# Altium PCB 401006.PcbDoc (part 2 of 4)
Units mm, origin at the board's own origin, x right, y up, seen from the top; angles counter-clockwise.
Board outline 117 x 63.5 mm, 4 copper layers (Top Layer, Mid-Layer 1, Mid-Layer 2, Bottom Layer), stack 1.68 mm thick; 205 components, 151 nets, 838 pads, 1570 vias.
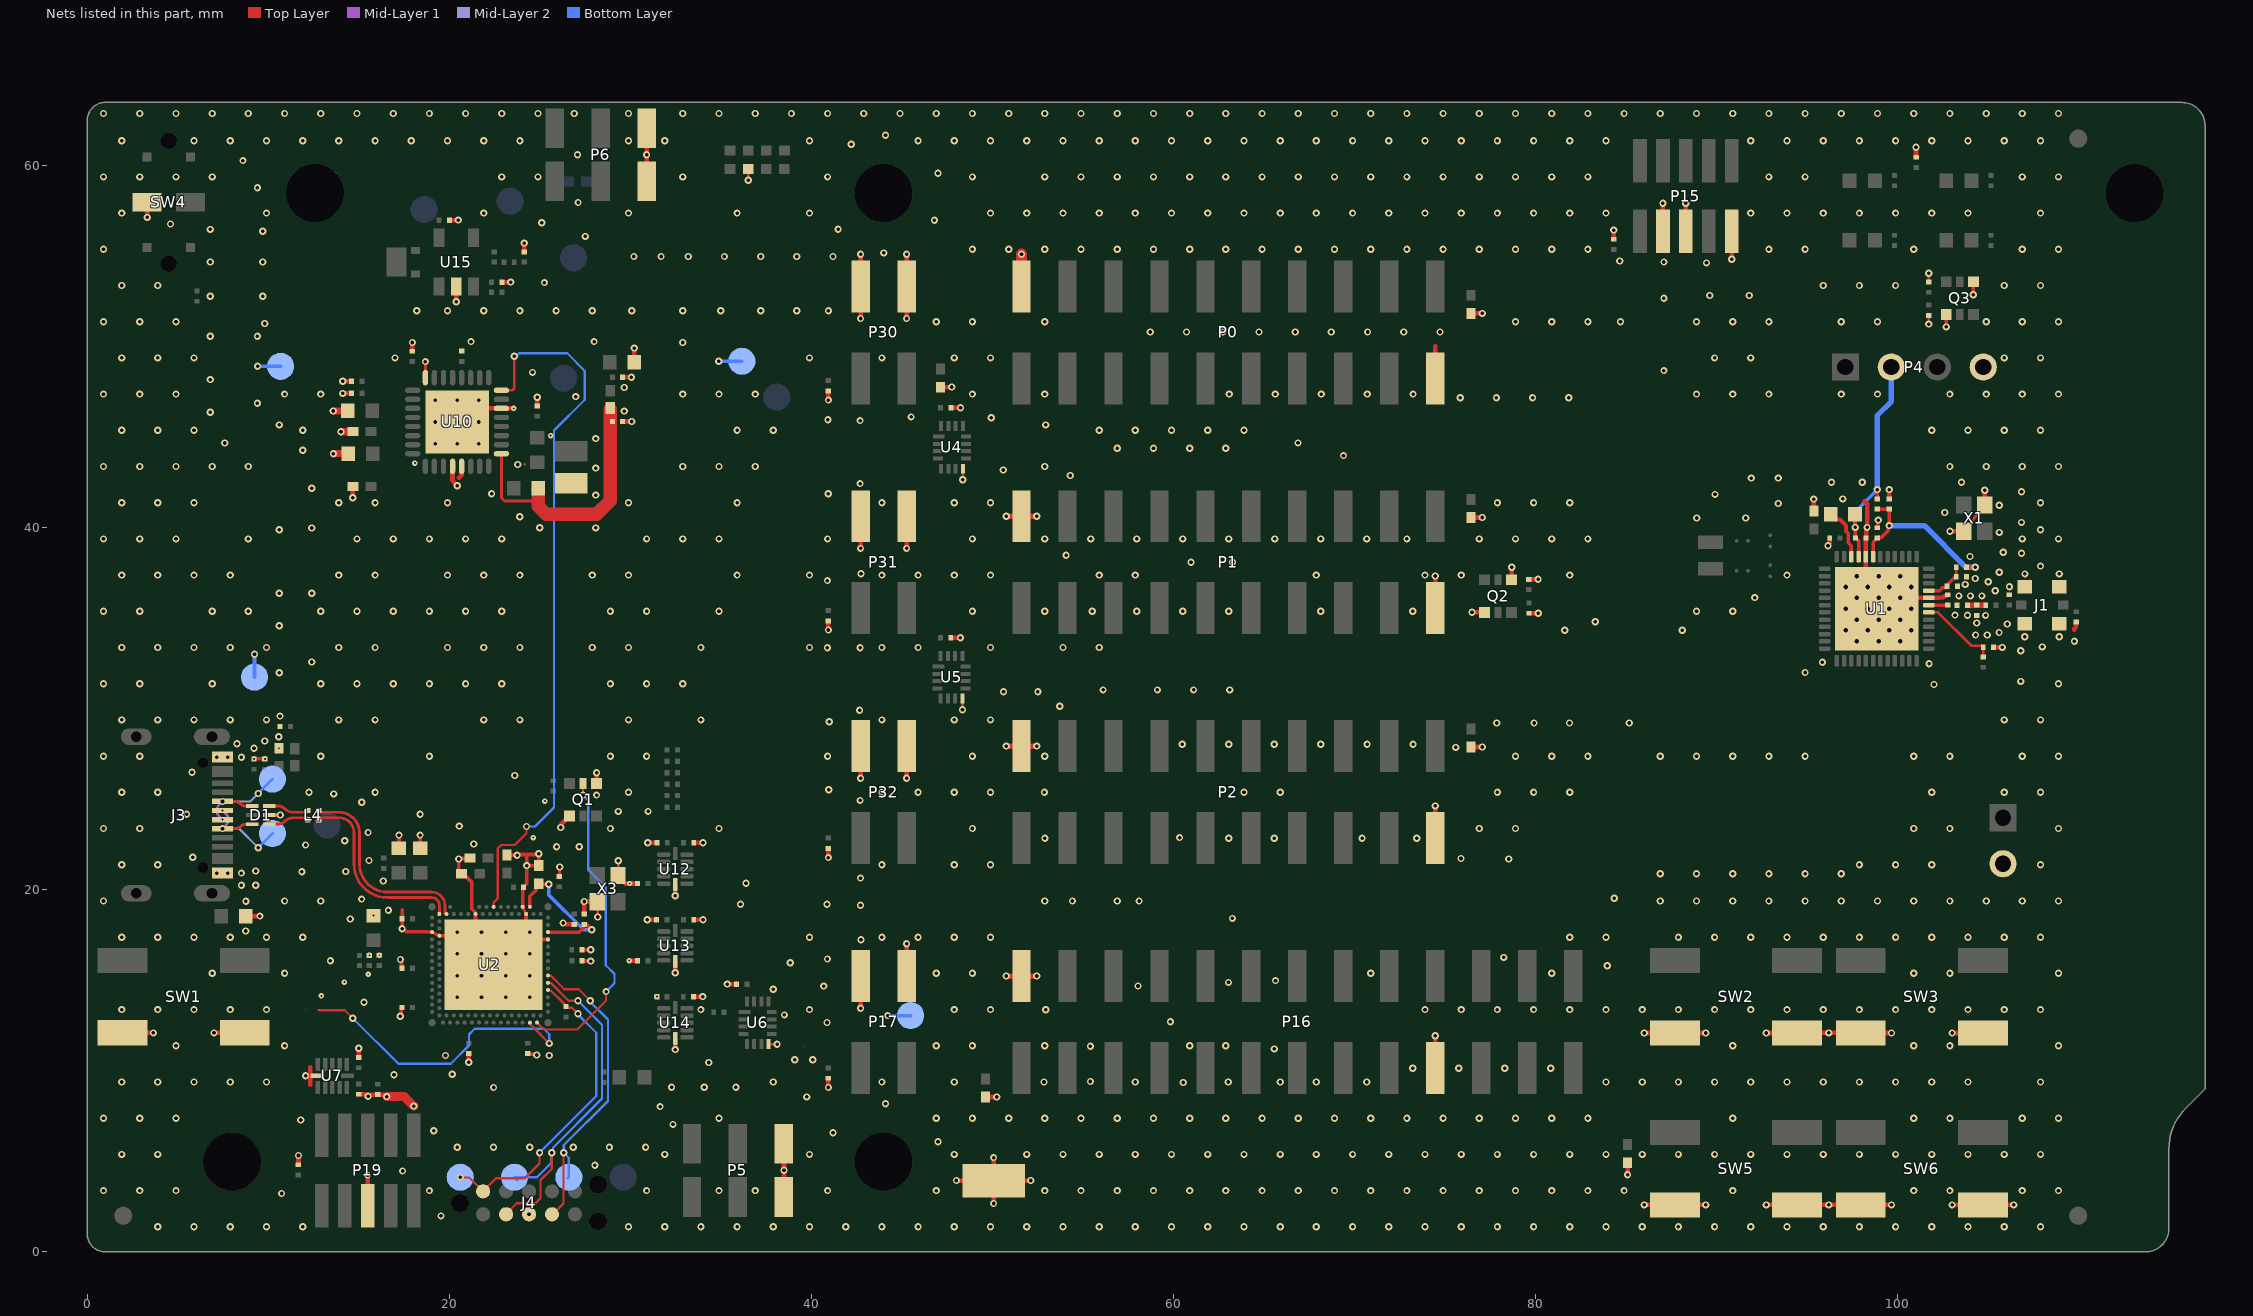
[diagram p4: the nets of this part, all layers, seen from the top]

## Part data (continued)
C41: library part C0402-100n, "Capacitor, X7R, ±10%", Manufacturer=N.A., Part number IPS=00000005296, Part number NEMS=100200184
C42 C43 C54 C58: library part C0603-4µ7-10V-X7S, "Capacitor, X7S, ±10%, 10V", Manufacturer=N.A., Part number IPS=00000001779, Part number NEMS=100200351, Supplier Part Number 1=445-14258-1-ND
C47: library part C0402-1µ0-16V-X5R, "Capacitor, Ceramic, X5R, ±10%, 16V", Manufacturer=Murata, Manufacturer Part Number=GRT155R61C105KE01D, Part number IPS=N.A., Part number NEMS=100200452, Supplier Part Number 1=490-12255-1-ND
C59: library part C0603-10n-100V-X7R, "Capacitor, X7R, ±10%, 100V", Manufacturer=Murata, Manufacturer Part Number=GCM188R72A103KA37D, Part number IPS=N.A., Part number NEMS=100200349, Supplier Part Number 1=490-4781-1-ND
D1: "TVS DIODE 5.5VWM 6XSON", Manufacturer=Nexperia, Part number IPS=N.A., Part number NEMS=101300202, Supplier Part Number 1=1727-4161-1-ND
FB1: library part FB0201-120R@100M-200mA-BLM03AG121SN1D, "Ferrite Bead, 120 Ohm @ 100MHz, 200mA, 500 mOhm Max", Manufacturer=Murata, Manufacturer Part Number=BLM03AG121SN1D, Part number IPS=N.A., Part number NEMS=100300419, Supplier Part Number 1=490-5622-1-ND
FB2 R1: library part R0201-0R-5%-0.05W-RC0201JR-070RL, "0 Ohms Jumper 0.05W, 1/20W Chip Resistor 0201 (0603 Metric) Moisture Resistant Thick Film", Manufacturer=Yageo, Manufacturer Part Number=RC0201JR-070RL, Part number IPS=N.A., Part number NEMS=100100652, Supplier Part Number 1=311-0.0NCT-ND
FB3 FB4: library part FB0402-120R@100M-500mA, "Ferrite Bead, 120 Ohm @ 100MHz, 500mA, 250 mOhm Max", Manufacturer=Murata, Manufacturer Part Number=BLM15AG121SN1D, Part number IPS=00000009954, Part number NEMS=100300099, Part number Norautron=265230631, Supplier Part Number 1=490-1005-1-ND
Fid1 Fid2 Fid3: library part Fid-Mark, "Fiducial Mark", Manufacturer=N.A., Part number NEMS=100500073
H1 H2 H3 H4 H5: library part MountingHole_3.2_M3, "Mounting hole, 3.2mm, M3, no annular", Manufacturer=N.A., Part number NEMS=101200008
J1: "Coaxial Connector with Switch", Manufacturer=Murata, Part number IPS=00000009955, Part number NEMS=100500400, Part number Norautron=26030338, Supplier Part Number 1=490-4981-1-ND
J3: library part SD-80259-1021, "USB-C Receptacle, 16 Pin, USB 2.0", Manufacturer="Bellweather Electronic Corp.", Part number IPS=N.A., Part number NEMS=100500830
J4: library part TC2050-IDC-NLFP, "CBL PLUG-OF-NAILS 10-PIN", Manufacturer="Tag-Connect LLC", Part number IPS=N.A., Part number NEMS=100500463, Supplier Part Number 1=TC2050-IDC-NL-ND
JP1: library part "SHUNT JUMPER 2.54mm Black Vertical", "Shunt Jumper 2.54mm Black, open top", Manufacturer=WCON, Manufacturer Part Number=3710-6001OS0B05, Part number IPS=N.A., Part number NEMS=100500728
L1: library part L0603-4µ7-MLZ1608M4R7WT000, "Inductor, 120mA, ±20%, 0.65R", Manufacturer="TDK Corporation", Manufacturer Part Number=MLZ1608M4R7WT000, Part number IPS=N.A., Part number NEMS=100300440, Supplier Part Number 1=445-6390-2-ND
L2: library part L0201-2n6-HQ-Murata, "Inductor, 600mA, ±0.1ｎH, 120mOhm", Manufacturer=Murata, Part number IPS=N.A., Part number NEMS=100300213, Supplier Part Number 1=490-13907-1-ND
L3: library part L0201-3n3-HQ-Murata, "Inductor, 500mA, ±0.1ｎH, 170mOhm", Manufacturer=Murata, Part number IPS=N.A., Part number NEMS=100300220, Supplier Part Number 1=490-13921-1-ND
L4: "2 Line Common Mode Choke, 90Ohm @ 100MHz, Imax=100mA, DCR=4Ohm, VDC=5V,  -40°C ~ 85°C", Manufacturer="Murata Electronics", Part number IPS=N.A., Part number NEMS=100300513, Supplier Part Number 1=490-DLM0NSM900HY2DCT-ND
L8: library part L0806-2µ2-2500mA-73mOhm-CIGT201610EH2R2MNE, "Inductor, Irms=2.5A, Isat=2.9A, ±20%, DCR=73mΩ", Manufacturer="Samsung Electro-Mechanics America", Manufacturer Part Number=CIGT201610EH2R2MNE, Part number IPS=N.A., Part number NEMS=100300400, Part number Norautron=26521789, Supplier Part Number 1=1276-6901-1-ND
LABEL1: library part Label_12x12, "PCA version label, stick-on, 12x12mm", Manufacturer="Ellco Etikett", Manufacturer Part Number=A33512‐01, Part number IPS=N.A., Part number NEMS=101200028
LABEL2: library part Label_20x40, "Early Access Label", Manufacturer=NA, Part number IPS=N.A., Part number NEMS=101200035
LD1 LD2 LD3 LD4 LD5: library part "VS 25C7M5", "LED, Green, 0603, 573nm, Vf=2.0V, 24mcd, - 40 to +85°C", Manufacturer="Victory Electronics", Part number IPS="00000001274, 00000009961", Part number NEMS=101400097, Part number Norautron=26313411, Supplier Part Number 1=N.A.
LOGO1: library part "Nordic Logo lying", "Nordic logo lying", Manufacturer=N.A., Part number NEMS=101100001
LOGO2: "Segger logo, small size", Manufacturer=N.A., Part number NEMS=101100004
LOGO3: library part "WEEE Symbol 3x4.5mm", "WEEE Directive symbol", Manufacturer=N.A., Part number NEMS=101100006
NT2: library part "2 pin starpoint", "Starpoint", Manufacturer=N.A., Part number NEMS=100500603
P0 P1 P2: library part "Pin Header 2x10 SMD, 2.54mm", "Pin Header 2x10, 2.54mm (100mil) SMD", Manufacturer=WCON, Manufacturer Part Number=1125-1210S0M116CR09, Part number IPS=N.A., Part number NEMS=100500738
P3: "Pin List 1x2, 2.54mm (100mil)", Manufacturer=N.A., Part number NEMS=100500297
P4: "Pin List 1x4, 2.54mm (100mil)", Manufacturer=N.A., Part number NEMS=100500309
P5 P6: library part "Pin List 1x3 SMD", "Pin List 1x3, 2.54mm (100mil), SMD", Manufacturer=WCON, Manufacturer Part Number=1125-1103S0M116CR04, Part number IPS=N.A., Part number NEMS=100500306, Part number Norautron=26470016
P15 P19: library part "Pin Header 2x5 SMD, 1.27mm, KS", "Pin Header 2x5, 1.27mm (50mil), SMD, Keying Shroud", Manufacturer=WCON, Manufacturer Part Number=3132-10MS0BK00R5, Part number IPS=N.A., Part number NEMS=100500261
P16: library part "Pin Header 2x13 SMD, 2.54mm", "Pin Header 2x13, 2.54mm (100mil) SMD", Manufacturer=WCON, Manufacturer Part Number=1125-1213S0M116CR09, Part number IPS=N.A., Part number NEMS=100500908
P17 P30 P31 P32: "Pin Header 2x2, SMD, 2.54mm (100mil)", Manufacturer=WCON, Manufacturer Part Number=1125-1202S0M116CR03, Part number IPS=N.A., Part number NEMS=100500770
Q1 Q2 Q3: "MOSFET 2N-CH 60V 0.17A TSSOP6 (SOT363)", Manufacturer=Nexperia, Manufacturer Part Number=NX138AKSX, Part number IPS=N.A., Part number NEMS=101300207, Supplier Part Number 1=1727-2732-2-ND
Q4: library part PBSS4330PA,115, "30V, 3A, 2.1W, G=270, NPN Transistor", Manufacturer=Nexperia, Part number IPS=N.A., Part number NEMS=101300184, Supplier Part Number 1=1727-5112-1-ND‎
R2 R3 R19 R20: library part R0201-680, "Resistor, ±1%, 0.05W", Manufacturer=N.A., Part number NEMS=100100040
R4 R37 R41 R42: library part R0201-10k, "Resistor, ±1%, 0.05W", Manufacturer=N.A., Part number IPS=00000001255, Part number NEMS=100100065, Part number Norautron=26107101
R5: library part R0201-560, "Resistor, ±1%, 0.05W", Manufacturer=N.A., Part number NEMS=100100038
R6 R8 R13 R14 R15 R16 R21 R22 R31 R32 R56: library part R0201-100k, "Resistor, ±1%, 0.05W", Manufacturer=N.A., Part number IPS=00000001419, Part number NEMS=100100080, Part number Norautron=26108487
R7: library part R0201-47R, "Resistor, ±1%, 0.05W", Manufacturer=N.A., Part number IPS=00000004794, Part number NEMS=100100022, Part number Norautron=26108300
R9 R38: library part R0201-0R, "Resistor, ±5%, 0.05W", Manufacturer=N.A., Part number IPS=00000003245, Part number NEMS=100100001
R10 R11 R12 R18 R27: library part R0201-1M0, "Resistor, ±1%, 0.05W", Manufacturer=N.A., Part number IPS=00000001418, Part number NEMS=100100093, Part number Norautron=26107108
R24: library part R0402-TBD, "Chip Res 0402", Manufacturer=N.A., Part number NEMS=100100282
R25 R28 R29 R30: library part R0402-0R, "Resistor, ±5%, 0.063W", Manufacturer=N.A., Part number IPS=00000007128, Part number NEMS=100100109, Supplier Part Number 1=146-9661
R26: library part R0201-47k, "Resistor, ±1%, 0.05W", Manufacturer=N.A., Part number IPS=00000001423, Part number NEMS=100100076
R36: library part R0201-1k0, "Resistor, ±1%, 0.05W", Manufacturer=N.A., Part number IPS=00000005786, Part number NEMS=100100043
R40: library part R0201-2R2, "Resistor, ±1%, 0.05W", Manufacturer=N.A., Part number NEMS=100100006, Part number Norautron=26470029
R43: library part R0201-33k, "Resistor, ±1%, 0.05W", Manufacturer=N.A., Part number IPS=00000001708, Part number NEMS=100100073
SB1: Manufacturer=N.A., Part number NEMS=100500458
SB2: library part "Solderbridge Shorted", "Shorted Solderbridge", Manufacturer=N.A., Part number NEMS=100500459
SB3 SB4: library part "Solderbridge Shorted 0.4mm", "Shorted Solderbridge", Manufacturer=N.A., Part number NEMS=100500561
SB5 SB6: library part "Solderbridge 0.4mm", Manufacturer=N.A., Part number NEMS=100500560
SW1 SW2 SW3 SW5 SW6: library part Switch-PB-6.2x6.3mm-SMD, "Tactile Switch, SPNO, SMD, 160gf, 6.2x6.3x2.5mm", Manufacturer=Dailywell, Manufacturer Part Number=TS604VM1-025BR-R, Part number IPS=00000007812, Part number NEMS="101500001, 101500133", Part number Norautron=N.A.
SW4: library part Switch-Slide-RA-J-Lead-DPDT-8.5x3.5mm_C&K, "SMD slide Switch (ON-ON)", Manufacturer=C&K, Manufacturer Part Number=JS202011JAQN, Part number IPS=00000007811, Part number NEMS=101500037, Part number Norautron=N.A., Supplier Part Number 1=CKN10722CT-ND
TP1 TP3 TP4 TP5 TP6 TP8 TP9 TP10 TP11 TP12 TP13 TP14 TP15 TP16 TP17 TP18: library part TP_SMD_Ø1.5MM, "1.5mm circular SMD testpad", Manufacturer="Nordic Semiconductor", Manufacturer Part Number=N.A., Part number NEMS=100500477
TP22: library part "TP - S1751-46R", "PC TEST POINT TIN SMD L", Manufacturer=Harwin, Manufacturer Part Number=S1751-46R, Part number IPS=N.A., Part number NEMS=100500525, Supplier Part Number 1=952-1478-1-ND
U1: "Multi-protocol Bluetooth Low Energy, IEEE 802.15.4 and 2.4GHz proprietary Wireless MCU", Manufacturer="Nordic Semiconductor", Part number IPS=N.A., Part number NEMS=102000422
U2: "Multi-protocol Bluetooth Low Energy, IEEE 802.15.4, ANT and 2.4GHz proprietary system-on-chip", Manufacturer="Nordic Semiconductor", Part number IPS=N.A., Part number NEMS=102000153
U4 U5 U6: "Low-Capacitance, 1:1 (SPST) 4-Channel, analog switch", Manufacturer="Texas Instruments", Manufacturer Part Number=TMUX1511RSVR, Part number IPS=N.A., Part number NEMS=101900847, Supplier Part Number 1=296-53443-2-ND
U7 U12 U13 U14: library part TXB0104RUTR, "4-Bit Bidirectional Level-Shifter/Voltage Translator with Automatic Direction Sensing", Manufacturer="Texas Instruments", Part number IPS=N.A., Part number NEMS=101900856, Supplier Part Number 1=296-25888-2-ND
U10: "Li-Ion/Li-Polymer USB-C battery charger with high efficiency buck regulators, LDOs or load switches, LED drivers, TWI and VBUSOUT", Manufacturer="Nordic Semiconductor", Part number IPS=N.A., Part number NEMS=102000291
U15: library part TLV271CW5-7, "Dual rail to rail CMOS Amplifier", Manufacturer="Diodes Incorporated", Part number IPS=N.A., Part number NEMS=101900398, Supplier Part Number 1=TLV271CW5-7DICT-ND
X1: library part XTAL_SMD2016_32MHz_8pF_Kyocera, "XTAL SMD 2016, 32MHz, Cl=8pF, Tot: ±40ppm", Manufacturer=Kyocera, Manufacturer Part Number=CX2016DB32000D0WZRC1, Part number IPS=00000007827, Part number NEMS=101600039, Part number Norautron=26511136, Supplier Part Number 1=1253-1586-1-ND
X2: library part XTAL_SMD2012_32.768kHz_9pF_TXC, "XTAL SMD 2012, 32.768kHz, 9pF, ±20ppm", Manufacturer="TXC Corporation", Manufacturer Part Number=9HT11-32.768KDZC-T, Part number IPS=N.A., Part number NEMS=101600107, Supplier Part Number 1=887-1426-2-ND
X3: library part XTAL_SMD2016_32MHz_8pF_Golledge, "XTAL SMD 2016, 32MHz, Cl=8pF, Tol: ±10ppm, Stab: ±15ppm", Manufacturer=Golledge, Manufacturer Part Number=MP06003, Part number IPS=00000001431, Part number NEMS=101600041, Part number Norautron=N.A.

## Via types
v1: diameter 0.4, hole 0.2, Top Layer to Bottom Layer, tented both sides, 1458 vias
v2: diameter 0.3, hole 0.1, Top Layer to Mid-Layer 1, tented top, 71 vias
v3: diameter 0.5, hole 0.25, Top Layer to Bottom Layer, tented both sides, 24 vias
v4: diameter 0.3, hole 0.1, Top Layer to Mid-Layer 1, tented both sides, 17 vias

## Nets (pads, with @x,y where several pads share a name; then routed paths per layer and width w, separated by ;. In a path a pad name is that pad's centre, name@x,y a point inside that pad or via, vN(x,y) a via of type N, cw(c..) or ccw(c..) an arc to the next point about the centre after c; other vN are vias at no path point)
ANT: C6.2 L2.1 U1.31 | length 0.9
  Top Layer w0.2: U1.31@101.893,35.73 102.75,35.73 C6.2@102.751,35.729
DBGR''_N: D1.3 L4.1 | length 2.3
  Top Layer w0.153: D1.3@10.065,24.634 10.567,24.634 cw(c10.567,24.164) 10.899,24.496 ccw(c11.408,25.005) 11.408,24.285 12.101,24.285 ccw(c12.101,24.384) L4.1@12.2,24.384
DBGR''_P: D1.1 L4.2 | length 2.3
  Top Layer w0.153: D1.1@10.065,23.634 10.567,23.634 ccw(c10.567,24.104) 10.899,23.772 cw(c11.408,23.263) 11.408,23.982 12.101,23.982 cw(c12.101,23.884) L4.2@12.2,23.884
DBGR'_N: D1.4 J3.A7 J3.B7 TP17.1 | length 6.2
  Top Layer w0.153: J3.B7@7.49,24.884 8.127,24.884 cw(c8.127,24.318) 8.527,24.718 ccw(c8.73,24.921) 8.73,24.634 D1.4@9.135,24.634
  Mid-Layer 1 w0.127: v2(7.485,23.884) 7.271,24.098 cw(c7.544,24.372) 7.157,24.372 cw(c7.604,24.372) 7.288,24.687 v1(7.485,24.884)
  Mid-Layer 2 w0.125: v1(7.485,24.884) 9.015,24.884 v1(9.455,25.324)
  Bottom Layer w0.153: v1(9.455,25.324) TP17.1@10.24,26.115
DBGR'_P: D1.6 J3.A6 J3.B6 TP18.1 | length 6.5
  Top Layer w0.153: v1(7.485,23.384) 8.174,23.384 ccw(c8.174,23.873) 8.519,23.528 cw(c8.776,23.271) 8.776,23.634 D1.6@9.135,23.634
  Mid-Layer 1 w0.127: v1(7.485,23.384) 7.682,23.581 ccw(c7.366,23.896) 7.813,23.896 ccw(c7.426,23.896) 7.699,24.17 v4(7.485,24.384)
  Mid-Layer 2 w0.125: v1(7.485,23.384) 8.393,23.384 v1(9.455,22.322)
  Bottom Layer w0.153: v1(9.455,22.322) TP18.1@10.24,23.113
DBGR_BUTTON: SB2.2 U2.AL27 | length 17.4
  Top Layer w0.125: SB2.2@12.8,13.364 12.815,13.35 14.237,13.35 v1(14.675,12.912) ; U2.AL27@24.46,12.664 24.46,12.637 24.51,12.587 24.51,12.555 24.631,12.434 24.631,12.427 v1(25.54,11.518)
  Top Layer w0.15: U2.AL27@24.46,12.622 U2.AL27@24.46,12.637
  Bottom Layer w0.125: v1(14.675,12.912) 17.2,10.387 20.087,10.387 21.1,11.4 21.1,12.009 21.416,12.325 25.244,12.325 25.54,12.03 v1(25.54,11.518)
DBGR_LED: Q1.2 U2.AL29 | length 17.4
  Top Layer w0.125: U2.AL29@24.86,12.664 25.237,12.288 27.083,12.288 28.663,13.868 28.663,14.368 v1(28.675,14.381) ; v1(27.401,25.234) Q1.2@27.401,25.71
  Bottom Layer w0.125: v1(27.401,25.234) 27.693,24.942 27.693,21.097 28.658,20.131 28.658,15.831 29.14,15.348 29.14,14.834 v1@28.675,14.369
DBGR_N: L4.4 U2.B4 | length 11.2
  Top Layer w0.153: L4.4@12.8,24.384 ccw(c12.898,24.384) 12.898,24.285 13.925,24.285 cw(c13.925,23.158) 15.053,23.158 15.053,21.422 ccw(c16.6,21.422) 16.6,19.875 19.033,19.875 cw(c19.033,19.138) 19.77,19.138 19.77,18.755 ccw(c19.86,18.755) U2.B4@19.86,18.664
DBGR_P: L4.3 U2.B2 | length 10.7
  Top Layer w0.153: L4.3@12.8,23.884 cw(c12.898,23.884) 12.898,23.982 13.925,23.982 cw(c13.925,23.158) 14.75,23.158 14.75,21.422 ccw(c16.6,21.422) 16.6,19.572 19.033,19.572 cw(c19.033,19.138) 19.467,19.138 19.467,18.664 U2.B2@19.46,18.664
DBGR_RESET: J4.10 R6.1 TP4.1 U2.AC31 | length 17.6
  Top Layer w0.125: v1(20.616,4.115) 21.107,4.115 J4.10@21.878,3.344 22.609,4.075 24.2,4.075 25.001,4.876 v1(25.001,5.475) ; U2.AC31@25.46,14.464 25.479,14.445 25.616,14.445 26.372,13.689 26.372,13.628 26.517,13.483 26.792,13.483 v1(27.125,13.15)
  Bottom Layer w0.125: v1(25.001,5.475) 28.132,8.605 28.132,12.107 27.125,13.114 v1(27.125,13.15)
DBGR_SWDCLK: J4.4 TP6.1 U2.W31 | length 17.8
  Top Layer w0.125: U2.W31@25.46,15.264 25.471,15.254 25.624,15.254 26.363,14.515 27.16,14.515 v1(27.8,13.875) ; J4.4@25.688,2.074 25.724,2.074 26.324,2.674 26.324,5.459 v1(26.34,5.475)
  Bottom Layer w0.125: TP6.1@26.558,4.067 TP6.1@26.564,4.062 ; TP6.1@26.616,4.125 26.616,5.198 v1(26.34,5.475) 26.34,5.903 28.775,8.339 28.775,12.832 v1@27.8,13.808
DBGR_SWDIO: J4.2 TP5.1 U2.AA31 | length 20.4
  Top Layer w0.125: J4.2@23.148,2.074 23.148,2.099 23.74,2.69 24.771,2.69 25.053,2.972 25.053,3.968 25.667,4.582 v1(25.667,5.475) ; U2.AA31@25.46,14.864 25.471,14.854 25.624,14.854 26.603,13.875 v1(27.125,13.875)
  Bottom Layer w0.125: TP5.1@23.616,4.125 24.851,4.125 25.667,4.94 v1(25.667,5.475) 25.738,5.547 25.738,5.76 28.452,8.473 28.452,12.548 v1(27.125,13.875)
  Bottom Layer w0.15: TP5.1@23.616,4.115 TP5.1@23.759,3.972
DCC: L1.1 U1.46 | length 2.8
  Top Layer w0.2: L1.1@96.316,40.758 96.316,40.733 96.591,40.458 96.834,40.458 97.169,40.123 97.169,39.819 97.296,39.692 97.296,39.187 97.468,39.014 U1.46@97.468,38.555
DECA: C2.2 C12.2 FB1.2 FB2.2 U1.43 | length 9.8
  Top Layer w0.2: U1.43@98.668,38.555 98.668,39.204 C12.2@98.896,39.432 98.931,39.467 99.119,39.467 99.499,39.847 99.499,40.066 v1(99.556,40.123) C2.2@99.556,41.032 FB1.2@98.896,41.032 ; FB2.2@103.83,37.821 v1(104.307,37.821)
  Bottom Layer w0.3: v1(99.556,40.123) 101.504,40.124 103.807,37.821 v1(104.307,37.821)
DECD: C1.2 FB1.1 L1.2 P4.2 U1.45 | length 12.5
  Top Layer w0.2: L1.2@97.677,40.798 v1(97.677,40.022) 97.677,39.461 C1.2@97.698,39.439 97.698,39.424 97.733,39.389 97.748,39.389 97.868,39.269 97.868,38.78 U1.45@97.868,38.555 ; FB1.1@98.896,41.602 v1(98.896,42.11)
  Bottom Layer w0.2: v1(97.677,40.022) 97.677,40.891 v1(98.896,42.11)
  Bottom Layer w0.3: v1(98.896,42.11) 98.896,46.202 99.674,46.98 P4.2@99.674,48.884
DERF: C5.2 C13.2 FB2.1 U1.33 | length 2.2
  Top Layer w0.15: C13.2@103.26,37.297 FB2.1@103.26,37.821
  Top Layer w0.2: U1.33@101.893,36.53 102.356,36.53 102.525,36.699 C5.2@102.716,36.699 ; C5.2@102.753,36.779 102.788,36.814 102.788,36.883 103.153,37.247 103.225,37.247 103.26,37.282 C13.2@103.26,37.297
GND: C1.1 C2.1 C3.1 C5.1 C6.1 C9.1 C10.2 C11.1 C12.1 C13.1 C14.2 C15.2 C16.1 C18.2 C20.2 C22.2 C23.1 C25.1 C26.1 C28.1 C29.2 C30.2 C31.2 C32.1 C33.2 C34.2 C35.2 C36.2 C37.2 C38.1 C39.1 C40.2 C41.1 C42.2 C43.2 C44.2 C45.1 C46.1 C47.1 C48.1 C49.2 C50.1 C51.1 C52.1 C53.1 C54.2 C55.1 C56.1 C57.1 C58.2 C59.2 C62.1 C63.1 C64.1 C67.2 C68.1 C69.2 C70.1 C72.2 C73.1 C74.2 C75.2 C76.2 C77.2 C78.2 C79.2 C80.2 C81.2 C82.1 C83.1 C84.1 D1.2 J1.2 J3.A1 J3.A12 J4.3 NT2.1 P0.2 P0.19 P1.2 P1.19 P2.2 P2.19 P3.2 P4.4 P5.1 P6.1 P15.3 P15.5 P15.9 P16.2 P16.19 P17.2 P17.4 P19.5 P30.2 P30.4 P31.2 P31.4 P32.2 P32.4 Q1.1 Q1.4 Q2.1 Q2.4 Q3.1 Q3.4 R4.1 R7.2 R10.2 R11.2 R12.2 R18.1 R26.2 R27.2 R30.2 R32.2 R37.1 R42.1 R56.2 SW1.1 SW2.1 SW3.1 SW4.2 SW5.1 SW6.1 TP12.1 TP13.1 TP14.1 TP15.1 TP22.1 U1.32 U1.44 U1.49 U2.104 U2.A25 U2.B12 U2.B26 U2.G1 U2.H2 U2.J31 U4.8 U5.8 U6.8 U7.6 U10.6 U10.16 U10.28 U10.29 U10.33 U12.6 U13.6 U14.6 U15.2 X1.2 X1.4 X3.2 X3.4 | length 169.9
  Top Layer w0.15: U10.16@18.678,48.31 U10.16@18.692,48.296 v1(18.692,49.183) ; C37.2@26.096,20.744 26.103,20.751 26.103,21.258 v1(26.11,21.265) ; v1(28.21,18.497) X3.4@28.21,19.315 ; X3.2@29.35,20.821 v1(29.35,21.608) ; v1(36.525,59.207) R30.2@36.525,59.83 ; U6.8@37.65,11.475 v1(38.121,11.475) ; v1(48.36,29.952) U5.8@48.36,30.561 ; v1(48.378,42.653) U4.8@48.378,43.262 ; v1(101.743,51.254) R27.2@101.743,51.729 ; R11.2@101.743,53.585 v1(101.743,54.06) ; X1.4@104.03,40.209 X1.2@104.48,40.859
  Top Layer w0.165: U2.A25@24.06,19.064 U2.B26@24.26,18.664
  Top Layer w0.187: U2.G1@19.06,17.664 U2.H2@19.46,17.464 U2.104@20.16,17.464 ; 21.245,20.052 21.245,18.96 21.453,18.752 21.453,18.672 U2.B12@21.46,18.664
  Top Layer w0.188: 18.183,17.694 18.832,17.694 18.856,17.669 19.055,17.669 U2.G1@19.06,17.664
  Top Layer w0.2: v4(9.225,27.235) v4(9.825,27.235) ; D1.2@10.065,24.134 v1(10.673,24.134) ; C42.2@17.231,22.302 v1(17.231,23.024) ; v1(17.308,13.017) 17.365,13.074 17.365,13.436 C20.2@17.428,13.499 ; v1(17.313,16.149) 17.369,16.094 17.369,15.659 C18.2@17.404,15.624 ; 17.404,18.9 17.404,18.864 C80.2@17.404,18.401 v1(17.404,17.852) 17.485,17.852 17.644,17.694 18.183,17.694 ; C43.2@18.4,22.302 v1(18.4,23.025) ; v1@20.529,21.735 20.529,21.041 20.679,20.891 C45.1@20.694,20.891 ; v1(20.538,21.706) 20.562,21.73 21.236,21.73 C39.1@21.262,21.756 ; C45.1@20.719,20.916 20.894,20.741 20.932,20.741 21.243,20.429 21.243,20.054 21.245,20.052 ; U2.A25@24.06,19.064 24.06,19.987 24.085,20.012 24.085,20.134 24.285,20.334 v1(24.285,21.34) ; 24.262,21.951 24.285,21.929 v1(24.285,21.34) ; C34.2@24.343,10.954 24.378,10.919 24.806,10.919 v1(24.85,10.875) ; v1(24.96,21.988) 24.957,21.984 24.957,21.343 C32.1@24.953,21.34 v1(24.285,21.34) ; C12.1@98.896,40.002 98.921,40.027 98.921,40.403 v1(98.947,40.428) ; v1@102.705,51.076 Q3.4@102.705,51.793 ; v1(104.205,52.876) Q3.1@104.205,53.593
  Top Layer w0.203: R7.2@27.345,16.687 v1(27.823,16.687) ; C35.2@27.353,16.078 27.36,16.071 27.816,16.071 v1(27.823,16.064)
  Top Layer w0.225: U2.104@21.46,17.264 U2.B12@21.46,18.664 ; C31.2@23.15,21.905 C31.2@23.16,21.915 ; C31.2@23.211,21.915 23.751,21.915 v1(23.759,21.907) 23.804,21.951 24.262,21.951 24.924,21.951 v1(24.96,21.988) ; U2.B26@24.26,18.664 24.26,17.264 U2.J31@25.46,17.264
  Top Layer w0.25: v1(12.075,9.725) U7.6@12.7,9.725 ; 12.34,9.244 12.34,10.2 ; C14.2@15.004,8.707 15.014,8.697 15.36,8.697 15.457,8.6 v1(15.525,8.6) 15.593,8.6 15.675,8.682 16.054,8.682 R18.1@16.064,8.692 16.074,8.682 16.391,8.682 16.493,8.58 v1(16.56,8.58) ; v1(26.299,18.167) 26.367,18.167 26.433,18.101 26.899,18.101 C36.2@26.909,18.091 ; v1(32.5,11.175) U14.6@32.5,11.8 ; v1(32.5,15.425) U13.6@32.5,16.05 ; v1(32.5,19.675) U12.6@32.5,20.3 ; C49.2@35.87,14.804 C49.2@35.88,14.794 ; v1(96.178,39.006) 96.178,39.073 96.264,39.159 96.264,39.428 C10.2@96.274,39.438 ; 98.185,41.47 98.337,41.317 98.337,39.954 98.278,39.895 98.278,39.449 C1.1@98.268,39.439 U1.44@98.268,38.41 U1.49@98.268,37.33 ; U1.49@100.672,36.13 U1.32@101.748,36.13 102.1,36.13 ; 102.323,36.13 102.1,36.13 ; C6.1@102.763,36.277 102.512,36.155 102.322,36.144 102.1,36.13 ; 109.789,34.36 109.789,34.427 109.855,34.493 109.855,34.785 109.865,34.795 C38.1@109.88,34.795
  Top Layer w0.254: SW1.1@1.963,12.097 v1(3.665,12.097) ; v1(3.321,57.15) SW4.2@3.321,57.988 ; v1(7.011,12.097) SW1.1@8.713,12.097 ; C59.2@8.775,18.552 v1(9.548,18.552) ; C73.1@11.679,4.816 v1(11.679,5.322) ; v1(14.132,47.425) C70.1@14.615,47.425 ; v1(14.132,48.091) R4.1@14.615,48.091 ; v1(14.684,41.665) C68.1@14.684,42.275 ; C53.1@15.004,10.744 v1(15.004,11.25) ; v1(15.498,4.244) 15.501,4.241 15.501,2.553 P19.5@15.504,2.55 ; R26.2@17.973,49.753 v1(17.973,50.236) ; C69.2@20.02,57 v1(20.503,57) ; U10.28@20.192,43.396 20.192,42.592 20.446,42.338 v1(20.446,42.329) ; v1(20.4,52.487) U15.2@20.4,53.325 ; 20.547,42.771 20.691,42.915 U10.29@20.692,43.396 ; v1(21.089,10.471) 21.09,10.473 21.09,10.952 C22.2@21.092,10.954 ; v1(21.642,47.046) 21.642,47.019 22.065,46.596 U10.6@22.892,46.596 v4(23.574,46.596) ; C72.2@22.92,53.575 v1(23.402,53.575) ; R37.1@24.151,55.245 v1(24.151,55.727) ; C56.1@24.867,46.731 v1(24.867,47.214) ; v1(26.17,23.445) 26.198,23.473 26.198,23.63 Q1.4@26.651,24.083 ; C33.2@27.459,18.661 27.459,19.359 28.165,19.359 X3.4@28.181,19.344 ; Q1.1@28.151,25.883 v1(28.151,26.467) ; X3.2@29.35,20.821 29.35,20.725 29.725,20.35 R32.2@30.415,20.35 ; C57.1@29.59,45.874 v1(30.098,45.874) ; C25.1@29.59,48.321 v1(30.072,48.321) ; v2(29.958,16.09) R56.2@30.415,16.09 ; C58.2@30.225,49.139 v1(30.225,49.927) ; P6.1@30.912,59.141 v1(30.912,60.614) P6.1@30.912,62.071 ; v1(30.953,18.354) C76.2@31.461,18.354 ; v1(30.973,22.604) C74.2@31.481,22.604 ; C79.2@33.505,14.104 v1(34.013,14.104) ; C77.2@33.518,18.344 v1(34.026,18.344) ; C75.2@33.518,22.604 v1(34.026,22.604) ; v1(35.372,14.794) C49.2@35.88,14.794 ; P5.1@38.5,3.035 v1(38.5,4.508) P5.1@38.5,5.965 ; v1(40.956,9.082) C83.1@40.956,9.59 ; v1(40.956,21.782) C52.1@40.956,22.29 ; v1(40.956,34.355) C55.1@40.956,34.863 ; v1(40.956,47.055) C62.1@40.956,47.563 ; v1(42.734,13.462) P17.2@42.734,15.24 ; v1(42.734,26.162) P32.2@42.734,27.94 ; v1(42.734,38.862) P31.2@42.734,40.64 ; v1(42.734,51.562) P30.2@42.734,53.34 v1(42.734,55.118) ; P17.4@45.274,15.24 v1(45.274,17.018) ; v1(45.274,26.162) P32.4@45.274,27.94 ; v1(45.274,38.862) P31.4@45.274,40.64 ; v1(45.274,51.562) P30.4@45.274,53.34 v1(45.274,55.118) ; C50.1@47.15,47.769 47.154,47.773 47.759,47.773 v1(47.763,47.777) ; C15.2@47.713,33.928 v1(48.246,33.928) ; C81.2@47.718,46.628 v1(48.252,46.628) ; v1(48.025,3.941) TP22.1@50.082,3.941 ; C84.1@49.643,8.556 v1(50.253,8.556) ; v1(50.082,2.671) TP22.1@50.082,3.941 ; v1(50.082,5.211) TP22.1@50.082,3.941 ; v1(52.14,3.941) TP22.1@50.082,3.941 ; P16.19@74.484,10.16 v1(74.484,11.938) ; P2.19@74.484,22.86 v1(74.484,24.638) ; P1.19@74.484,35.56 v1(74.484,37.338) ; P0.19@74.484,48.26 74.484,50.038 ; C51.1@76.466,27.893 v1(77.075,27.893) ; C82.1@76.466,40.568 v1(77.075,40.568) ; C28.1@76.466,51.845 v1(77.075,51.845) ; v1(76.511,35.331) Q2.4@77.2,35.331 ; Q2.1@78.7,37.131 v1(78.7,37.821) ; R10.2@79.652,37.156 v1(80.16,37.156) ; R12.2@79.658,35.282 v1(80.166,35.282) ; C63.1@84.346,55.94 v1(84.346,56.448) ; v1(85.105,4.258) C41.1@85.105,4.926 ; v1(86.019,2.594) SW5.1@87.721,2.594 v1(89.423,2.594) ; v1(86.019,12.094) SW2.1@87.721,12.094 v1(89.423,12.094) ; P15.3@87.054,56.38 v1(87.054,57.929) ; P15.5@88.324,56.38 v1(88.324,57.929) ; v1(90.864,54.831) P15.9@90.864,56.38 ; v1(92.769,2.594) SW5.1@94.471,2.594 94.474,2.597 v1(96.223,2.597) 97.979,2.597 SW6.1@97.982,2.594 v1(99.684,2.594) ; v1(92.769,12.094) SW2.1@94.471,12.094 ; SW2.1@94.474,12.097 v1(96.223,12.097) SW3.1@97.979,12.097 ; C3.1@95.391,40.928 v1(95.391,41.589) ; SW3.1@97.982,12.094 v1(99.684,12.094) ; C2.1@99.556,41.602 v1(99.556,42.11) ; C64.1@101.039,60.47 v1(101.039,61.025) ; v1(102.918,39.809) X1.4@103.68,39.809 ; v1(103.031,2.594) SW6.1@104.732,2.594 v1(106.434,2.594) ; v1(103.031,12.094) SW3.1@104.732,12.094 ; X1.2@104.83,41.259 v1(104.83,42.072) ; C16.1@105.323,33.393 v1(105.805,33.393)
  Top Layer w0.305: v1(50.786,15.24) P16.2@51.624,15.24 v1(52.462,15.24) ; v1(50.786,27.94) P2.2@51.624,27.94 v1(52.462,27.94) ; v1(50.786,40.64) P1.2@51.624,40.64 v1(52.462,40.64)
  Top Layer w0.4: v1(13.6,46.456) 14.401,46.456 C26.1@14.404,46.459 ; v1@13.61,44.1 C54.2@14.425,44.1 ; v1(14.032,45.304) 14.037,45.308 14.679,45.308 C23.1@14.684,45.313
  Top Layer w0.5: v1(16.56,8.58) 17.53,8.58 v1(18.055,8.055)
  Top Layer w0.6: P0.2@51.624,53.34 v1(51.624,55.118)
  Bottom Layer w0.2: TP14.1@9.25,31.75 v1(9.25,33.02) ; v1(9.423,48.92) TP12.1@10.693,48.92 ; v1(34.904,49.2) TP15.1@36.174,49.2 ; v1(44.226,13.056) TP13.1@45.496,13.056
  other v1: 3.912,1.387 5.912,1.387 7.912,1.387 9.912,1.387 11.912,1.387 29.912,1.387 31.912,1.387 33.912,1.387 35.912,1.387 37.912,1.387 39.912,1.387 41.912,1.387 43.912,1.387 45.912,1.387 47.912,1.387 49.912,1.387 51.912,1.387 53.912,1.387 55.912,1.387 57.912,1.387 59.912,1.387 61.912,1.387 63.912,1.387 65.912,1.387 67.912,1.387 69.912,1.387 71.912,1.387 73.912,1.387 75.912,1.387 77.912,1.387 79.912,1.387 81.912,1.387 83.912,1.387 85.912,1.387 87.912,1.387 89.912,1.387 91.912,1.387 93.912,1.387 95.912,1.387 97.912,1.387 99.912,1.387 101.912,1.387 103.912,1.387 105.912,1.387 107.912,1.387 19.557,1.987 24.418,2.074 10.749,3.225 0.912,3.387 2.912,3.387 4.912,3.387 18.912,3.387 30.912,3.387 34.912,3.387 36.912,3.387 40.912,3.387 46.912,3.387 52.912,3.387 54.912,3.387 56.912,3.387 58.912,3.387 60.912,3.387 62.912,3.387 64.912,3.387 66.912,3.387 68.912,3.387 70.912,3.387 72.912,3.387 74.912,3.387 76.912,3.387 78.912,3.387 80.912,3.387 82.912,3.387 84.912,3.387 90.912,3.387 100.912,3.387 102.912,3.387 106.912,3.387 108.912,3.387 17.432,4.471 28.057,4.787 1.912,5.387 3.912,5.387 31.912,5.387 39.912,5.387 47.912,5.387 51.912,5.387 53.912,5.387 55.912,5.387 57.912,5.387 59.912,5.387 61.912,5.387 63.912,5.387 65.912,5.387 67.912,5.387 69.912,5.387 71.912,5.387 73.912,5.387 75.912,5.387 77.912,5.387 79.912,5.387 81.912,5.387 83.912,5.387 85.912,5.387 87.912,5.387 89.912,5.387 91.912,5.387 93.912,5.387 95.912,5.387 97.912,5.387 99.912,5.387 101.912,5.387 103.912,5.387 105.912,5.387 107.912,5.387 20.457,5.787 22.457,5.787 24.457,5.787 26.857,5.787 28.857,5.787 30.857,5.787 47.012,6.087 41.212,6.587 19.157,6.687 32.367,7.041 11.812,7.287 0.912,7.387 2.912,7.387 4.912,7.387 34.912,7.387 46.912,7.387 48.912,7.387 50.912,7.387 52.912,7.387 54.912,7.387 56.912,7.387 58.912,7.387 60.912,7.387 62.912,7.387 64.912,7.387 66.912,7.387 68.912,7.387 70.912,7.387 72.912,7.387 74.912,7.387 76.912,7.387 78.912,7.387 80.912,7.387 82.912,7.387 90.912,7.387 100.912,7.387 102.912,7.387 106.912,7.387 108.912,7.387 31.656,8.027 44.112,8.187 39.759,8.56 22.459,9.08 32.291,9.094 34.094,9.094 35.847,9.094 60.559,9.36 1.912,9.387 3.912,9.387 5.912,9.387 7.912,9.387 9.912,9.387 37.912,9.387 43.912,9.387 47.912,9.387 52.863,9.385 57.912,9.387 63.048,9.385 65.912,9.387 67.912,9.387 70.694,9.385 83.912,9.387 85.912,9.387 87.912,9.387 89.912,9.387 91.912,9.387 93.912,9.387 95.912,9.387 97.912,9.387 99.912,9.387 101.912,9.387 103.912,9.387 107.912,9.387 55.428,9.41 16.957,9.787 20.173,9.817 73.234,10.147 75.774,10.147 78.314,10.147 80.854,10.147 34.348,10.465 39.098,10.618 40.089,10.618 19.8,10.85 25.54,10.85 65.588,11.214 55.428,11.366 4.912,11.387 10.912,11.387 46.912,11.387 48.912,11.387 52.912,11.387 60.912,11.387 62.912,11.387 90.912,11.387 100.912,11.387 102.912,11.387 108.912,11.387 40.876,12.675 59.848,12.712 38.525,13.091 52.964,13.373 1.912,13.387 3.912,13.387 5.912,13.387 7.912,13.387 9.912,13.387 33.912,13.387 39.912,13.387 47.912,13.387 49.912,13.387 73.912,13.387 75.912,13.387 77.912,13.387 79.912,13.387 81.912,13.387 83.912,13.387 85.912,13.387 87.912,13.387 89.912,13.387 91.912,13.387 93.912,13.387 95.912,13.387 97.912,13.387 99.912,13.387 101.912,13.387 103.912,13.387 105.912,13.387 107.912,13.387 15.298,13.793 20.46,14.064 21.794,14.064 23.127,14.064 24.46,14.064 37.907,14.513 40.698,14.682 58.057,14.687 63.057,14.887 65.657,14.987 20.46,15.264 21.794,15.264 23.127,15.264 24.46,15.264 6.912,15.387 10.912,15.387 46.912,15.387 48.912,15.387 70.912,15.387 80.912,15.387 100.912,15.387 102.912,15.387 108.912,15.387 83.978,15.811 38.844,15.977 13.444,16.079 40.902,16.18 78.263,16.268 20.46,16.464 21.794,16.464 23.127,16.464 24.46,16.464 42.756,17.247 1.912,17.387 3.912,17.387 5.912,17.387 7.912,17.387 9.912,17.387 11.912,17.387 39.912,17.387 43.912,17.387 45.912,17.387 47.912,17.387 49.912,17.387 81.912,17.387 83.912,17.387 87.912,17.387 89.912,17.387 91.912,17.387 93.912,17.387 95.912,17.387 97.912,17.387 99.912,17.387 101.912,17.387 103.912,17.387 105.912,17.387 107.912,17.387 20.46,17.664 21.794,17.664 23.127,17.664 24.46,17.664 8.771,17.727 14.536,18.39 63.275,18.422 16.65,18.879 42.73,19.152 40.875,19.199 36.101,19.203 8.775,19.375 27.46,19.359 0.912,19.387 10.912,19.387 12.912,19.387 52.912,19.387 54.436,19.387 56.912,19.387 58.119,19.387 86.912,19.387 88.912,19.387 90.912,19.387 92.912,19.387 94.912,19.387 96.912,19.387 98.912,19.387 100.912,19.387 102.912,19.387 104.912,19.387 106.912,19.387 108.912,19.387 15.169,19.491 84.361,19.533 8.529,20.25 9.318,20.25 36.406,20.371 16.361,20.49 42.73,20.651 86.912,20.887 88.912,20.887 90.912,20.887 92.912,20.887 94.912,20.887 96.912,20.887 7.168,20.921 7.779,20.925 8.529,20.925 11.869,21.006 14.292,21.012 9.318,21.041 1.912,21.387 3.912,21.387 43.912,21.387 47.912,21.387 49.912,21.387 97.912,21.387 99.912,21.387 101.912,21.387 107.912,21.387 15.575,21.625 78.542,21.704 75.901,21.729 5.845,21.797 25.941,22.378 27.186,22.378 12.073,22.48 21.369,22.53 14.242,22.718 52.914,22.847 63.074,22.847 65.588,22.847 70.44,22.847 73.462,22.847 60.357,22.887 15.525,23.169 0.912,23.387 2.912,23.387 28.912,23.387 34.912,23.387 48.912,23.387 76.912,23.387 78.912,23.387 100.912,23.387 102.912,23.387 108.912,23.387 20.556,23.521 5.5,24.175 18.397,24.181 29.345,24.334 30.996,24.334 15.175,24.844 42.705,24.943 28.15,25.234 13.625,25.3 1.912,25.387 3.912,25.387 12.26,25.387 15.912,25.387 29.912,25.387 43.912,25.387 45.912,25.387 47.912,25.387 49.912,25.387 52.888,25.387 63.912,25.387 65.912,25.387 77.912,25.387 79.912,25.387 81.912,25.387 101.912,25.387 105.912,25.387 107.912,25.387 40.978,25.528 23.63,26.315 5.796,26.498 7.171,27.325 7.779,27.325 8.529,27.325 0.912,27.387 2.912,27.387 12.912,27.387 18.912,27.387 28.912,27.387 30.912,27.387 40.912,27.387 48.912,27.387 52.912,27.387 78.912,27.387 80.912,27.387 82.912,27.387 86.912,27.387 88.912,27.387 90.912,27.387 92.912,27.387 94.912,27.387 100.912,27.387 102.912,27.387 106.912,27.387 108.912,27.387 9.225,27.825 75.616,27.869 8.283,28.065 60.503,28.047 63.068,28.047 65.583,28.047 68.148,28.047 70.714,28.047 73.254,28.047 9.824,28.225 10.596,28.452 77.883,29.216 79.94,29.216 81.896,29.216 85.198,29.216 41.003,29.287 1.912,29.387 3.912,29.387 5.912,29.387 7.912,29.387 9.912,29.387 13.912,29.387 15.912,29.387 21.912,29.387 23.912,29.387 29.912,29.387 33.912,29.387 43.912,29.387 47.912,29.387 49.912,29.387 105.912,29.387 107.912,29.387 10.662,29.6 42.68,29.922 53.73,30.145 50.63,30.945 52.53,30.945 56.13,31.045 59.13,31.045 61.13,31.045 63.13,31.045 102.03,31.345 0.912,31.387 2.912,31.387 6.912,31.387 12.912,31.387 14.912,31.387 16.912,31.387 18.912,31.387 20.912,31.387 22.912,31.387 28.912,31.387 30.912,31.387 32.912,31.387 108.912,31.387 106.818,31.514 10.612,31.987 94.912,32.01 101.759,32.493 12.412,32.587 95.868,32.569 106.818,33.214 1.912,33.387 3.912,33.387 5.912,33.387 7.912,33.387 9.912,33.387 13.912,33.387 15.912,33.387 19.912,33.387 21.912,33.387 23.912,33.387 27.912,33.387 29.912,33.387 33.912,33.387 39.912,33.387 40.902,33.376 42.705,33.376 43.912,33.387 45.912,33.387 49.912,33.387 53.912,33.387 55.912,33.387 108.005,33.42 109.788,33.73 107.044,33.989 108.955,33.989 104.331,34.079 104.969,34.079 105.627,34.214 81.63,34.345 88.13,34.345 10.612,34.587 106.084,34.688 104.387,34.742 83.319,34.804 103.879,35.171 104.882,35.16 103.192,35.18 0.912,35.387 2.912,35.387 6.912,35.387 8.912,35.387 12.912,35.387 14.912,35.387 16.912,35.387 18.912,35.387 20.912,35.387 22.912,35.387 28.912,35.387 30.912,35.387 34.912,35.387 48.912,35.387 52.912,35.387 55.528,35.387 57.992,35.387 60.532,35.387 63.072,35.387 68.152,35.387 73.232,35.387 88.912,35.387 90.912,35.387 92.13,36.145 103.407,36.238 104.042,36.238 104.677,36.238 10.612,36.387 12.412,36.387 105.411,36.519 106.198,36.747 103.753,36.873 105.023,37.026 40.902,37.085 104.311,37.203 1.912,37.387 3.912,37.387 5.912,37.387 7.912,37.387 13.912,37.387 15.912,37.387 19.912,37.387 21.912,37.387 23.912,37.387 27.912,37.387 29.912,37.387 35.912,37.387 39.912,37.387 43.912,37.387 45.912,37.387 47.912,37.387 49.912,37.387 55.912,37.387 57.912,37.387 67.912,37.387 73.912,37.387 75.912,37.387 81.912,37.387 93.912,37.387 107.055,37.456 108.955,37.456 42.756,37.466 105.63,37.545 107.912,37.887 60.984,38.1 63.276,38.1 104.018,38.414 54.087,38.489 106.868,38.598 105.856,38.65 0.912,39.387 2.912,39.387 4.912,39.387 8.912,39.387 14.912,39.387 16.912,39.387 18.912,39.387 20.912,39.387 22.912,39.387 30.912,39.387 32.912,39.387 34.912,39.387 40.912,39.387 48.912,39.387 52.912,39.387 55.452,39.387 57.992,39.387 60.532,39.387 63.072,39.387 65.612,39.387 68.152,39.387 70.692,39.387 72.912,39.387 76.912,39.387 78.912,39.387 80.912,39.387 82.912,39.387 106.912,39.387 108.912,39.387 105.63,39.745 10.612,39.887 107.912,39.887 12.412,39.987 25.009,40.002 28.097,39.995 98.337,40.022 106.868,40.298 88.93,40.545 91.63,40.545 23.909,40.612 102.63,40.845 105.63,41.245 93.43,41.345 1.912,41.387 3.912,41.387 5.912,41.387 13.912,41.387 15.912,41.387 19.912,41.387 29.912,41.387 35.912,41.387 43.912,41.387 47.912,41.387 49.912,41.387 77.912,41.387 79.912,41.387 81.912,41.387 107.912,41.387 96.991,41.597 28.1,41.807 89.93,41.845 22.349,41.88 40.952,41.885 106.868,41.998 12.412,42.187 42.705,42.444 96.368,42.514 98.068,42.514 103.548,42.514 91.93,42.745 93.43,42.745 54.312,42.892 50.612,43.192 28.1,43.3 0.912,43.387 2.912,43.387 4.912,43.387 6.912,43.387 8.912,43.387 32.912,43.387 34.912,43.387 36.912,43.387 52.912,43.387 102.912,43.387 104.912,43.387 106.912,43.387 108.912,43.387 23.792,43.496 69.412,43.992 13.61,44.096 11.912,44.287 56.912,44.392 58.912,44.392 60.912,44.392 62.912,44.392 19.242,44.646 20.442,44.646 21.642,44.646 7.612,44.687 66.897,44.689 28.1,44.927 1.912,45.387 3.912,45.387 5.912,45.387 11.912,45.387 35.912,45.387 37.912,45.387 59.912,45.387 61.912,45.387 63.912,45.387 101.912,45.387 103.912,45.387 105.912,45.387 107.912,45.387 55.912,45.392 57.912,45.392 10.612,45.687 52.957,45.687 19.242,45.846 20.442,45.846 21.642,45.846 42.705,45.924 40.927,45.975 49.957,46.087 45.524,46.127 6.812,46.387 29.675,46.45 9.412,46.887 19.242,47.046 20.442,47.046 75.857,47.187 77.857,47.187 79.857,47.187 81.857,47.187 27,47.25 0.912,47.387 2.912,47.387 4.912,47.387 10.912,47.387 12.912,47.387 32.912,47.387 34.912,47.387 36.912,47.387 48.912,47.387 52.912,47.387 63.097,47.387 65.637,47.387 68.177,47.387 70.717,47.387 73.257,47.387 88.912,47.387 90.912,47.387 92.912,47.387 96.912,47.387 98.912,47.387 102.912,47.387 104.912,47.387 106.912,47.387 108.912,47.387 29.675,47.75 6.812,48.187 24.612,48.587 87.112,48.687 1.912,49.387 3.912,49.387 5.912,49.387 17.012,49.387 39.912,49.387 43.912,49.387 47.912,49.387 49.912,49.387 89.912,49.387 91.912,49.387 105.912,49.387 107.912,49.387 32.912,50.236 21.212,50.287 28.012,50.287 6.812,50.587 9.412,50.587 58.74,50.82 60.74,50.82 62.74,50.82 64.74,50.82 66.74,50.82 68.74,50.82 70.74,50.82 72.74,50.82 74.74,50.82 102.705,51.1 9.812,51.287 0.912,51.387 2.912,51.387 4.912,51.387 46.912,51.387 48.912,51.387 52.912,51.387 78.912,51.387 80.912,51.387 82.912,51.387 84.712,51.387 88.912,51.387 90.912,51.387 92.912,51.387 96.912,51.387 98.912,51.387 104.912,51.387 106.912,51.387 108.912,51.387 18.212,51.987 19.912,51.987 21.912,51.987 23.912,51.987 25.912,51.987 27.912,51.987 30.098,51.987 32.912,51.987 35.012,51.987 37.215,51.987 39.212,51.987 40.956,51.987 87.112,52.687 6.812,52.787 9.712,52.787 89.644,52.833 91.829,52.833 1.912,53.387 3.912,53.387 95.912,53.387 97.912,53.387 99.912,53.387 105.912,53.387 107.912,53.387 25.268,53.546 89.466,54.636 6.812,54.687 9.712,54.687 87.112,54.687 84.666,54.738 30.212,54.987 31.712,54.987 33.212,54.987 35.212,54.987 37.212,54.987 39.212,54.987 41.212,54.987 44.012,55.187 0.912,55.387 48.912,55.387 50.912,55.387 52.912,55.387 54.912,55.387 56.912,55.387 58.912,55.387 60.912,55.387 62.912,55.387 64.912,55.387 66.912,55.387 68.912,55.387 70.912,55.387 72.912,55.387 74.912,55.387 76.912,55.387 78.912,55.387 80.912,55.387 82.912,55.387 92.912,55.387 94.912,55.387 100.912,55.387 106.912,55.387 108.912,55.387 27.521,56.098 9.712,56.387 6.812,56.487 41.492,56.488 4.612,56.787 25.123,56.855 46.812,56.987 1.912,57.387 9.912,57.387 21.912,57.387 29.912,57.387 35.912,57.387 39.912,57.387 49.912,57.387 51.912,57.387 53.912,57.387 55.912,57.387 57.912,57.387 59.912,57.387 61.912,57.387 63.912,57.387 65.912,57.387 67.912,57.387 69.912,57.387 71.912,57.387 73.912,57.387 75.912,57.387 77.912,57.387 79.912,57.387 81.912,57.387 83.912,57.387 91.912,57.387 93.912,57.387 95.912,57.387 97.912,57.387 99.912,57.387 101.912,57.387 103.912,57.387 107.912,57.387 27.127,57.97 9.412,58.787 0.912,59.387 2.912,59.387 4.912,59.387 6.912,59.387 22.912,59.387 24.912,59.387 32.912,59.387 40.912,59.387 48.912,59.387 52.912,59.387 54.912,59.387 56.912,59.387 58.912,59.387 60.912,59.387 62.912,59.387 64.912,59.387 66.912,59.387 68.912,59.387 70.912,59.387 72.912,59.387 74.912,59.387 76.912,59.387 78.912,59.387 80.912,59.387 82.912,59.387 92.912,59.387 94.912,59.387 106.912,59.387 108.912,59.387 47.012,59.587 8.612,60.287 27.094,60.609 42.212,61.187 1.912,61.387 5.912,61.387 7.912,61.387 9.912,61.387 11.912,61.387 13.912,61.387 15.912,61.387 17.912,61.387 19.912,61.387 21.912,61.387 23.912,61.387 29.912,61.387 31.912,61.387 39.912,61.387 45.912,61.387 47.912,61.387 49.912,61.387 51.912,61.387 53.912,61.387 55.912,61.387 57.912,61.387 59.912,61.387 61.912,61.387 63.912,61.387 65.912,61.387 67.912,61.387 69.912,61.387 71.912,61.387 73.912,61.387 75.912,61.387 77.912,61.387 79.912,61.387 81.912,61.387 83.912,61.387 91.912,61.387 93.912,61.387 95.912,61.387 97.912,61.387 99.912,61.387 101.912,61.387 103.912,61.387 105.912,61.387 107.912,61.387 44.112,61.687 0.912,62.887 2.912,62.887 4.912,62.887 6.912,62.887 8.912,62.887 10.912,62.887 12.912,62.887 14.912,62.887 16.912,62.887 18.912,62.887 20.912,62.887 22.912,62.887 24.912,62.887 26.912,62.887 29.912,62.887 32.912,62.887 34.912,62.887 36.912,62.887 38.912,62.887 40.912,62.887 42.912,62.887 44.912,62.887 46.912,62.887 48.912,62.887 50.912,62.887 52.912,62.887 54.912,62.887 56.912,62.887 58.912,62.887 60.912,62.887 62.912,62.887 64.912,62.887 66.912,62.887 68.912,62.887 70.912,62.887 72.912,62.887 74.912,62.887 76.912,62.887 78.912,62.887 80.912,62.887 82.912,62.887 84.912,62.887 86.912,62.887 88.912,62.887 90.912,62.887 92.912,62.887 94.912,62.887 96.912,62.887 98.912,62.887 100.912,62.887 102.912,62.887 104.912,62.887 106.912,62.887 108.912,62.887
  other v2: 31.479,14.104 15.601,16.385 16.146,16.386 15.826,18.576 29.983,20.35
  other v3: 97.768,33.73 98.968,33.73 100.168,33.73 97.168,34.33 98.368,34.33 99.568,34.33 100.768,34.33 97.768,34.93 98.968,34.93 100.168,34.93 97.168,35.53 98.368,35.53 99.568,35.53 100.768,35.53 97.768,36.13 98.968,36.13 100.168,36.13 97.168,36.73 98.368,36.73 99.568,36.73 100.768,36.73 97.768,37.33 98.968,37.33 100.168,37.33
  other v4: 12.947,14.144 14.215,14.907 15.531,15.336 24.655,22.884 25.297,24.901 10.6,27.825 18.109,43.578 25.61,45.096
LED_PWR_CTRL: U2.A17 U10.8 | length 39.3
  Top Layer w0.125: U2.A17@22.46,19.064 22.46,19.287 22.692,19.519 22.692,22.288 22.88,22.475 23.63,22.475 24.275,23.12 v1(24.275,23.5)
  Top Layer w0.15: U10.8@22.892,47.596 23.49,47.596 23.603,47.709 23.603,49.471 v1(23.6,49.475)
  Bottom Layer w0.125: v1(23.6,49.475) 23.696,49.475 23.861,49.64 26.523,49.64 27.5,48.663 27.5,47.075 25.8,45.375 25.8,24.55 24.75,23.5 v1(24.275,23.5)
NetC9_2: C9.2 L2.2 L3.1 | length 1
  Top Layer w0.3: L2.2@103.905,35.729 L3.1@104.87,35.729
NetC16_2: C16.2 R1.1 U1.30 | length 4.3
  Top Layer w0.15: U1.30@101.748,35.33 102.257,35.33 104.104,33.484 104.663,33.484 C16.2@104.753,33.393 R1.1@104.753,32.866
NetC27_2: C27.2 C57.2 FB3.1 L8.1 U10.1 | length 15.1
  Top Layer w0.15: U10.1@22.892,44.096 22.892,41.657 23.068,41.481 24.924,41.481
  Top Layer w0.75: C27.2@24.924,42.186 24.924,41.481 24.924,41.189 25.363,40.75 28.15,40.75 28.9,41.5 28.9,45.874 FB3.1@28.9,46.55
NetC32_2: C32.2 C33.1 U2.A27 U2.G31 | length 8.9
  Top Layer w0.15: C32.2@24.953,20.385 C32.2@25.032,20.306
  Top Layer w0.2: U2.A27@24.46,19.064 24.46,19.64 24.801,19.98 C32.2@24.801,20.381 ; C32.2@24.803,20.535 24.953,20.385 C32.2@24.953,20.34 ; C32.2@25.032,20.306 v1(25.512,20.306) ; U2.G31@25.46,17.664 27.185,17.664 27.409,17.889 27.409,18.056 27.444,18.091 C33.1@27.459,18.091 27.494,18.056 27.618,18.056 v1@27.884,17.79
  Bottom Layer w0.2: v1(25.512,20.306) 25.512,19.719 27.441,17.79 v1(27.885,17.79)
